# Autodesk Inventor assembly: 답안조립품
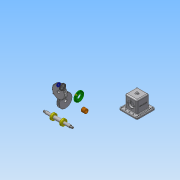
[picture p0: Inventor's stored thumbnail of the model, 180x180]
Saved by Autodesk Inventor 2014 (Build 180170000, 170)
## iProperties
Created: 2018-11
Part Number: 답안조립품
Document SubType Name: Assembly
Designer: 703
Author: 703
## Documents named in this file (13)
- C:\Users\user\Desktop\481107V1019\답안조립품.iam
- C:\Users\user\Desktop\481107V1019\본체.ipt
- C:\Users\user\Desktop\481107V1019\V벨트풀리.ipt
- C:\Users\user\Desktop\481107V1019\너트 M12x1.25.ipt
- C:\Users\user\Desktop\481107V1019\베어링 6203.ipt
- C:\Users\user\Desktop\481107V1019\볼트 M4.ipt
- C:\Users\user\Desktop\481107V1019\부시.ipt
- C:\Users\user\Desktop\481107V1019\스퍼기어.ipt
- C:\Users\user\Desktop\481107V1019\오일 실 26 38 8.ipt
- C:\Users\user\Desktop\481107V1019\와셔 12x24.ipt
- C:\Users\user\Desktop\481107V1019\축.ipt
- C:\Users\user\Desktop\481107V1019\커버.ipt
- C:\Users\user\Desktop\481107V1019\키 5x5x12.ipt
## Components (1 placed, 1 different names)
1. V벨트풀리:1
